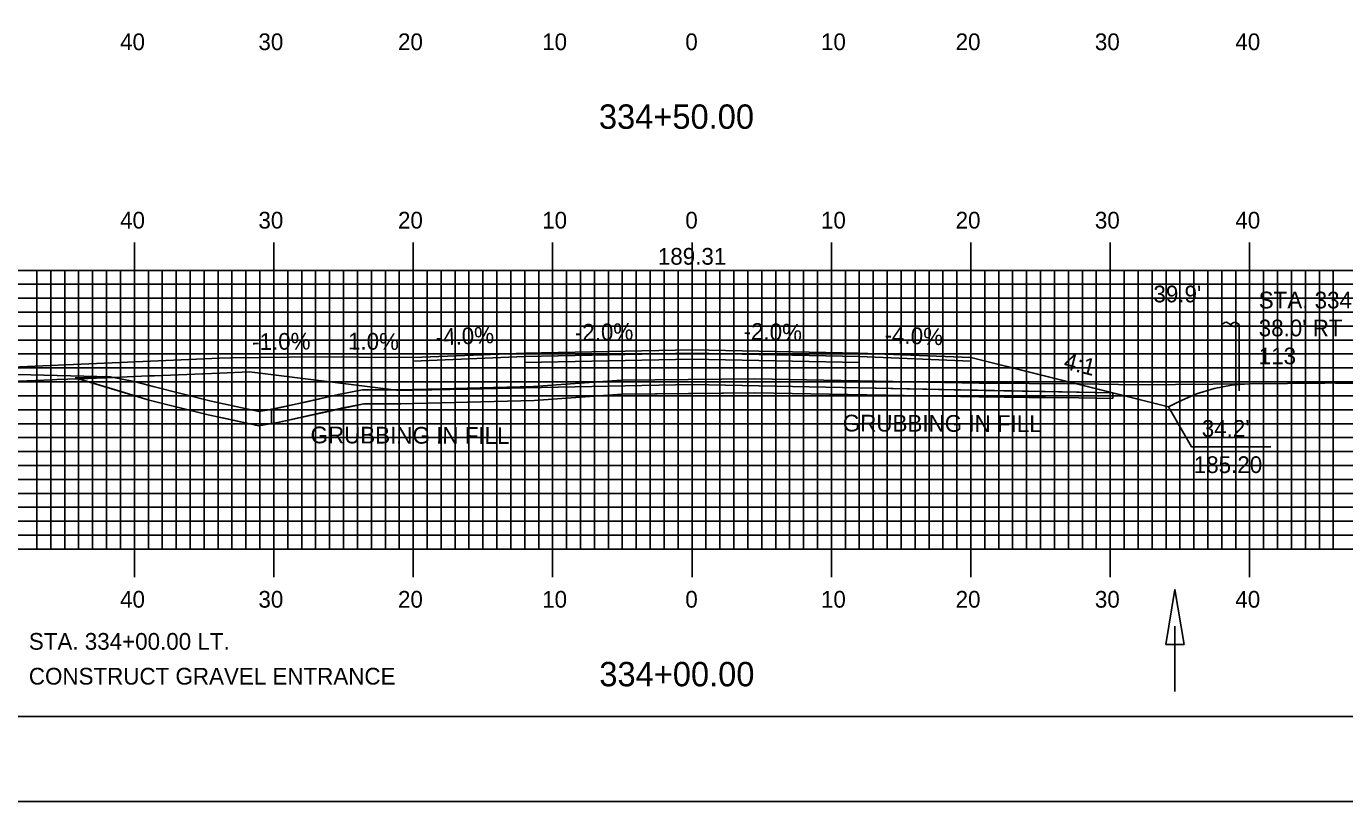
# Model space of a CAD drawing. Extents: x 1823179 to 1823522, y 442591 to 442811.
# Drawn here: x 1823297 to 1823391.6, y 442590.5 to 442646.2 of the extents above; entities that cross this region are included whole.
import ezdxf

# ---------------------------------------------------------------- set-up
doc = ezdxf.new("R2010")
doc.units = 0
for name, color, linetype in [('ANNOTATION', 7, 'Continuous'), ('BORDER', 7, 'Continuous'), ('D_Drainage_Ditch_Line', 7, 'Continuous'), ('D_Drainage_Text', 7, 'Continuous'), ('D_Roadway_Centerline', 7, 'Continuous'), ('D_Roadway_Centerline_Text', 7, 'Continuous'), ('D_Roadway_Drive_SubGrade', 7, 'Continuous'), ('D_Roadway_Edge_Shoulder', 7, 'Continuous'), ('D_Roadway_Edge_TW', 7, 'Continuous'), ('D_Roadway_FinishedGrade', 7, 'Continuous'), ('D_Roadway_Pavement', 7, 'Continuous'), ('D_Roadway_SlopeLines', 7, 'Continuous'), ('D_Roadway_SubGrade', 7, 'Continuous'), ('D_Text_Standard', 7, 'Continuous'), ('D_Utilities_Pole_Joint', 7, 'Continuous'), ('GRUBBING IN FILL', 7, 'Continuous'), ('H_V ANNOTATION', 7, 'Continuous'), ('MAJOR', 7, 'Continuous'), ('MINOR', 7, 'Continuous'), ('PLOT BOUNDARY', 7, 'Continuous'), ('S_Roadway_Centerline', 7, 'Continuous')]:
    doc.layers.add(name, color=color, linetype=linetype)

msp = doc.modelspace()

# ---------------------------------------------------------------- linework, layer by layer
at = {"layer": 'ANNOTATION'}
msp.add_line((1823310.906, 442622.367), (1823251.255, 442619.818), dxfattribs=at)
msp.add_lwpolyline([(1823386.318, 442615.997), (1823380.626, 442615.997), (1823378.97, 442618.867)], dxfattribs=at)
at = {"layer": 'BORDER'}
msp.add_lwpolyline([(1823195.196, 442596.665), (1823515.196, 442596.665), (1823515.196, 442806.665), (1823195.196, 442806.665)], close=True, dxfattribs=at)
at = {"layer": 'D_Drainage_Ditch_Line'}
msp.add_line((1823379.439, 442603.139), (1823379.439, 442598.44), dxfattribs=at)
msp.add_lwpolyline([(1823378.783, 442601.827), (1823380.095, 442601.827), (1823379.439, 442605.764)], close=True, dxfattribs=at)
at = {"layer": 'D_Roadway_Centerline'}
for points in [[(1823310.906, 442622.367), (1823310.907, 442622.367), (1823311.725, 442622.4), (1823311.741, 442622.4), (1823315.907, 442622.441), (1823318.796, 442622.47), (1823320.907, 442622.449), (1823324.796, 442622.41)], [(1823324.796, 442622.41), (1823332.796, 442622.73), (1823344.796, 442622.97), (1823356.796, 442622.73), (1823364.796, 442622.41), (1823374.97, 442619.867), (1823378.97, 442618.867), (1823379.739, 442619.251), (1823380.989, 442619.8), (1823382.239, 442620.195), (1823383.489, 442620.437), (1823384.739, 442620.526)]]:
    msp.add_lwpolyline(points, dxfattribs=at)
at = {"layer": 'D_Roadway_Drive_SubGrade'}
for p, q in [((1823323.796, 442620.05), (1823313.052, 442621.378)), ((1823324.796, 442620.07), (1823323.796, 442620.05))]:
    msp.add_line(p, q, dxfattribs=at)
msp.add_lwpolyline([(1823295.893, 442620.693), (1823298.932, 442620.815), (1823299.22, 442620.826), (1823300.798, 442620.889), (1823300.912, 442620.893), (1823302.64, 442620.962), (1823302.734, 442620.966), (1823305.825, 442621.09), (1823305.922, 442621.093), (1823306.235, 442621.106), (1823306.244, 442621.106), (1823309.709, 442621.245), (1823309.751, 442621.247), (1823310.917, 442621.293), (1823310.926, 442621.293), (1823313.052, 442621.378)], dxfattribs=at)
at = {"layer": 'D_Roadway_Edge_Shoulder'}
for points in [[(1823332.796, 442622.73), (1823324.796, 442622.41), (1823324.796, 442622.16), (1823332.796, 442622.48)], [(1823356.796, 442622.73), (1823364.796, 442622.41), (1823364.796, 442622.16), (1823356.796, 442622.48)]]:
    msp.add_lwpolyline(points, close=True, dxfattribs=at)
at = {"layer": 'D_Roadway_Edge_TW'}
msp.add_lwpolyline([(1823332.796, 442622.48), (1823332.796, 442622.73), (1823344.796, 442622.97), (1823356.796, 442622.73), (1823356.796, 442622.48), (1823344.796, 442622.72)], close=True, dxfattribs=at)
at = {"layer": 'D_Roadway_FinishedGrade'}
msp.add_line((1823324.796, 442622.41), (1823324.796, 442620.07), dxfattribs=at)
at = {"layer": 'D_Roadway_Pavement'}
msp.add_lwpolyline([(1823332.796, 442622.064), (1823332.796, 442622.48), (1823344.796, 442622.72), (1823356.796, 442622.48), (1823356.796, 442622.064), (1823344.796, 442622.304)], close=True, dxfattribs=at)
at = {"layer": 'D_Roadway_SlopeLines'}
for points in [[(1823364.796, 442622.41), (1823378.97, 442618.867)], [(1823378.97, 442618.867), (1823379.739, 442619.251), (1823380.989, 442619.8), (1823382.239, 442620.195), (1823383.489, 442620.437), (1823384.739, 442620.526)]]:
    msp.add_lwpolyline(points, dxfattribs=at)
at = {"layer": 'D_Roadway_SubGrade'}
msp.add_lwpolyline([(1823332.796, 442620.23), (1823324.796, 442620.07), (1823324.796, 442622.41), (1823324.796, 442622.16), (1823332.796, 442622.48), (1823344.796, 442622.72), (1823356.796, 442622.48), (1823364.796, 442622.16), (1823364.796, 442622.41), (1823374.97, 442619.867), (1823356.796, 442620.23), (1823344.796, 442620.47)], close=True, dxfattribs=at)
at = {"layer": 'D_Utilities_Pole_Joint'}
for p, q in [((1823382.796, 442624.777), (1823382.952, 442624.888)), ((1823383.264, 442624.888), (1823383.42, 442624.777)), ((1823383.576, 442624.888), (1823383.42, 442624.777)), ((1823384.046, 442624.777), (1823383.889, 442624.888)), ((1823382.796, 442620.02), (1823382.796, 442624.777)), ((1823383.42, 442624.777), (1823383.576, 442624.667)), ((1823383.889, 442624.667), (1823384.046, 442624.777)), ((1823384.046, 442620.02), (1823384.046, 442624.777))]:
    msp.add_line(p, q, dxfattribs=at)
for centre, start, end in [((1823383.108, 442624.667), 90, 125.26439), ((1823383.108, 442624.667), 54.73561, 90), ((1823383.733, 442624.667), 90, 125.26439), ((1823383.733, 442624.667), 54.73561, 90), ((1823383.733, 442624.888), 234.73561, 270), ((1823383.733, 442624.888), 270, 305.26439)]:
    msp.add_arc(centre, 0.271, start, end, dxfattribs=at)
at = {"layer": 'GRUBBING IN FILL'}
for p, q in [((1823374.97, 442619.867), (1823374.97, 442619.479)), ((1823374.97, 442619.867), (1823374.97, 442619.479)), ((1823314.621, 442617.669), (1823314.621, 442618.669)), ((1823314.621, 442617.669), (1823314.621, 442618.669))]:
    msp.add_line(p, q, dxfattribs=at)
for points in [[(1823300.549, 442620.952), (1823301.264, 442620.98), (1823302.728, 442621.039), (1823303.069, 442621.031), (1823303.929, 442620.856), (1823304.788, 442620.681), (1823305.429, 442620.531), (1823305.78, 442620.426), (1823306.131, 442620.321), (1823310.303, 442619.279), (1823313.294, 442618.634), (1823313.723, 442618.533), (1823314.302, 442618.63), (1823317.161, 442619.243), (1823319.441, 442619.76), (1823321.169, 442620.094), (1823322.532, 442620.094), (1823323.438, 442620.094), (1823323.796, 442620.05), (1823324.796, 442620.07), (1823328.796, 442620.15), (1823332.796, 442620.23), (1823338.796, 442620.35), (1823344.796, 442620.47), (1823344.796, 442619.833), (1823339.786, 442619.788), (1823333.462, 442619.34), (1823328.685, 442619.217), (1823323.908, 442619.095), (1823321.264, 442619.094), (1823315.073, 442617.745), (1823314.382, 442617.629), (1823313.69, 442617.514), (1823313.074, 442617.659), (1823311.575, 442617.982), (1823310.076, 442618.305), (1823307.971, 442618.831), (1823305.866, 442619.356), (1823303.207, 442620.154)], [(1823300.549, 442620.952), (1823301.264, 442620.98), (1823302.728, 442621.039), (1823303.069, 442621.031), (1823303.929, 442620.856), (1823304.788, 442620.681), (1823305.429, 442620.531), (1823305.78, 442620.426), (1823306.131, 442620.321), (1823310.303, 442619.279), (1823313.294, 442618.634), (1823313.723, 442618.533), (1823314.302, 442618.63), (1823317.161, 442619.243), (1823319.441, 442619.76), (1823321.169, 442620.094), (1823322.532, 442620.094), (1823323.438, 442620.094), (1823323.796, 442620.05), (1823324.796, 442620.07), (1823328.796, 442620.15), (1823332.796, 442620.23), (1823338.796, 442620.35), (1823344.796, 442620.47), (1823344.796, 442619.833), (1823339.786, 442619.788), (1823333.462, 442619.34), (1823328.685, 442619.217), (1823323.908, 442619.095), (1823321.264, 442619.094), (1823315.073, 442617.745), (1823314.382, 442617.629), (1823313.69, 442617.514), (1823313.074, 442617.659), (1823311.575, 442617.982), (1823310.076, 442618.305), (1823307.971, 442618.831), (1823305.866, 442619.356), (1823303.207, 442620.154)], [(1823344.796, 442620.47), (1823350.796, 442620.35), (1823356.796, 442620.23), (1823365.883, 442620.048), (1823374.97, 442619.867), (1823374.97, 442619.479), (1823372.553, 442619.521), (1823368.967, 442619.551), (1823365.382, 442619.581), (1823357.345, 442619.727), (1823349.308, 442619.873), (1823344.796, 442619.833)], [(1823344.796, 442620.47), (1823350.796, 442620.35), (1823356.796, 442620.23), (1823365.883, 442620.048), (1823374.97, 442619.867), (1823374.97, 442619.479), (1823372.553, 442619.521), (1823368.967, 442619.551), (1823365.382, 442619.581), (1823357.345, 442619.727), (1823349.308, 442619.873), (1823344.796, 442619.833)]]:
    msp.add_lwpolyline(points, close=True, dxfattribs=at)
for points in [[(1823300.549, 442620.952), (1823305.866, 442619.356), (1823310.076, 442618.305), (1823313.074, 442617.659), (1823313.69, 442617.514), (1823315.073, 442617.745), (1823319.647, 442618.781), (1823321.264, 442619.094), (1823323.908, 442619.095), (1823333.462, 442619.34), (1823339.786, 442619.788), (1823349.308, 442619.873), (1823365.382, 442619.581), (1823372.553, 442619.521), (1823374.97, 442619.479)], [(1823300.549, 442620.952), (1823305.866, 442619.356), (1823310.076, 442618.305), (1823313.074, 442617.659), (1823313.69, 442617.514), (1823315.073, 442617.745), (1823319.647, 442618.781), (1823321.264, 442619.094), (1823323.908, 442619.095), (1823333.462, 442619.34), (1823339.786, 442619.788), (1823349.308, 442619.873), (1823365.382, 442619.581), (1823372.553, 442619.521), (1823374.97, 442619.479)], [(1823314.621, 442617.669), (1823315.073, 442617.745), (1823319.647, 442618.781), (1823321.264, 442619.094), (1823323.438, 442619.094)], [(1823314.621, 442617.669), (1823315.073, 442617.745), (1823319.647, 442618.781), (1823321.264, 442619.094), (1823323.438, 442619.094)]]:
    msp.add_lwpolyline(points, dxfattribs=at)
at = {"layer": 'MAJOR'}
for p, q in [((1823304.796, 442630.669), (1823304.796, 442628.665)), ((1823314.796, 442630.669), (1823314.796, 442628.665)), ((1823324.796, 442630.669), (1823324.796, 442628.665)), ((1823334.796, 442630.669), (1823334.796, 442628.665)), ((1823344.796, 442630.669), (1823344.796, 442628.665)), ((1823354.796, 442630.669), (1823354.796, 442628.665)), ((1823364.796, 442630.669), (1823364.796, 442628.665)), ((1823374.796, 442630.669), (1823374.796, 442628.665)), ((1823384.796, 442630.669), (1823384.796, 442628.665)), ((1823204.796, 442628.665), (1823484.796, 442628.665)), ((1823204.796, 442628.665), (1823484.796, 442628.665)), ((1823304.796, 442608.665), (1823304.796, 442628.665)), ((1823314.796, 442608.665), (1823314.796, 442628.665)), ((1823324.796, 442608.665), (1823324.796, 442628.665)), ((1823334.796, 442608.665), (1823334.796, 442628.665)), ((1823344.796, 442608.665), (1823344.796, 442628.665)), ((1823354.796, 442608.665), (1823354.796, 442628.665)), ((1823364.796, 442608.665), (1823364.796, 442628.665)), ((1823374.796, 442608.665), (1823374.796, 442628.665)), ((1823384.796, 442608.665), (1823384.796, 442628.665)), ((1823204.796, 442623.665), (1823484.796, 442623.665)), ((1823204.796, 442618.665), (1823484.796, 442618.665)), ((1823204.796, 442613.665), (1823484.796, 442613.665)), ((1823204.796, 442608.665), (1823484.796, 442608.665)), ((1823204.796, 442608.665), (1823484.796, 442608.665)), ((1823304.796, 442606.661), (1823304.796, 442608.665)), ((1823314.796, 442606.661), (1823314.796, 442608.665)), ((1823324.796, 442606.661), (1823324.796, 442608.665)), ((1823334.796, 442606.661), (1823334.796, 442608.665)), ((1823344.796, 442606.661), (1823344.796, 442608.665)), ((1823354.796, 442606.661), (1823354.796, 442608.665)), ((1823364.796, 442606.661), (1823364.796, 442608.665)), ((1823374.796, 442606.661), (1823374.796, 442608.665)), ((1823384.796, 442606.661), (1823384.796, 442608.665))]:
    msp.add_line(p, q, dxfattribs=at)
at = {"layer": 'MINOR'}
for p, q in [((1823297.796, 442608.665), (1823297.796, 442628.665)), ((1823298.796, 442608.665), (1823298.796, 442628.665)), ((1823299.796, 442608.665), (1823299.796, 442628.665)), ((1823300.796, 442608.665), (1823300.796, 442628.665)), ((1823301.796, 442608.665), (1823301.796, 442628.665)), ((1823302.796, 442608.665), (1823302.796, 442628.665)), ((1823303.796, 442608.665), (1823303.796, 442628.665)), ((1823305.796, 442608.665), (1823305.796, 442628.665)), ((1823306.796, 442608.665), (1823306.796, 442628.665)), ((1823307.796, 442608.665), (1823307.796, 442628.665)), ((1823308.796, 442608.665), (1823308.796, 442628.665)), ((1823309.796, 442608.665), (1823309.796, 442628.665)), ((1823310.796, 442608.665), (1823310.796, 442628.665)), ((1823311.796, 442608.665), (1823311.796, 442628.665)), ((1823312.796, 442608.665), (1823312.796, 442628.665)), ((1823313.796, 442608.665), (1823313.796, 442628.665)), ((1823315.796, 442608.665), (1823315.796, 442628.665)), ((1823316.796, 442608.665), (1823316.796, 442628.665)), ((1823317.796, 442608.665), (1823317.796, 442628.665)), ((1823318.796, 442608.665), (1823318.796, 442628.665)), ((1823319.796, 442608.665), (1823319.796, 442628.665)), ((1823320.796, 442608.665), (1823320.796, 442628.665)), ((1823321.796, 442608.665), (1823321.796, 442628.665)), ((1823322.796, 442608.665), (1823322.796, 442628.665)), ((1823323.796, 442608.665), (1823323.796, 442628.665)), ((1823325.796, 442608.665), (1823325.796, 442628.665)), ((1823326.796, 442608.665), (1823326.796, 442628.665)), ((1823327.796, 442608.665), (1823327.796, 442628.665)), ((1823328.796, 442608.665), (1823328.796, 442628.665)), ((1823329.796, 442608.665), (1823329.796, 442628.665)), ((1823330.796, 442608.665), (1823330.796, 442628.665)), ((1823331.796, 442608.665), (1823331.796, 442628.665)), ((1823332.796, 442608.665), (1823332.796, 442628.665)), ((1823333.796, 442608.665), (1823333.796, 442628.665)), ((1823335.796, 442608.665), (1823335.796, 442628.665)), ((1823336.796, 442608.665), (1823336.796, 442628.665)), ((1823337.796, 442608.665), (1823337.796, 442628.665)), ((1823338.796, 442608.665), (1823338.796, 442628.665)), ((1823339.796, 442608.665), (1823339.796, 442628.665)), ((1823340.796, 442608.665), (1823340.796, 442628.665)), ((1823341.796, 442608.665), (1823341.796, 442628.665)), ((1823342.796, 442608.665), (1823342.796, 442628.665)), ((1823343.796, 442608.665), (1823343.796, 442628.665)), ((1823345.796, 442608.665), (1823345.796, 442628.665)), ((1823346.796, 442608.665), (1823346.796, 442628.665)), ((1823347.796, 442608.665), (1823347.796, 442628.665)), ((1823348.796, 442608.665), (1823348.796, 442628.665)), ((1823349.796, 442608.665), (1823349.796, 442628.665)), ((1823350.796, 442608.665), (1823350.796, 442628.665)), ((1823351.796, 442608.665), (1823351.796, 442628.665)), ((1823352.796, 442608.665), (1823352.796, 442628.665)), ((1823353.796, 442608.665), (1823353.796, 442628.665)), ((1823355.796, 442608.665), (1823355.796, 442628.665)), ((1823356.796, 442608.665), (1823356.796, 442628.665)), ((1823357.796, 442608.665), (1823357.796, 442628.665)), ((1823358.796, 442608.665), (1823358.796, 442628.665)), ((1823359.796, 442608.665), (1823359.796, 442628.665)), ((1823360.796, 442608.665), (1823360.796, 442628.665)), ((1823361.796, 442608.665), (1823361.796, 442628.665)), ((1823362.796, 442608.665), (1823362.796, 442628.665)), ((1823363.796, 442608.665), (1823363.796, 442628.665)), ((1823365.796, 442608.665), (1823365.796, 442628.665)), ((1823366.796, 442608.665), (1823366.796, 442628.665)), ((1823367.796, 442608.665), (1823367.796, 442628.665)), ((1823368.796, 442608.665), (1823368.796, 442628.665)), ((1823369.796, 442608.665), (1823369.796, 442628.665)), ((1823370.796, 442608.665), (1823370.796, 442628.665)), ((1823371.796, 442608.665), (1823371.796, 442628.665)), ((1823372.796, 442608.665), (1823372.796, 442628.665)), ((1823373.796, 442608.665), (1823373.796, 442628.665)), ((1823375.796, 442608.665), (1823375.796, 442628.665)), ((1823376.796, 442608.665), (1823376.796, 442628.665)), ((1823377.796, 442608.665), (1823377.796, 442628.665)), ((1823378.796, 442608.665), (1823378.796, 442628.665)), ((1823379.796, 442608.665), (1823379.796, 442628.665)), ((1823380.796, 442608.665), (1823380.796, 442628.665)), ((1823381.796, 442608.665), (1823381.796, 442628.665)), ((1823382.796, 442608.665), (1823382.796, 442628.665)), ((1823383.796, 442608.665), (1823383.796, 442628.665)), ((1823385.796, 442608.665), (1823385.796, 442628.665)), ((1823386.796, 442608.665), (1823386.796, 442628.665)), ((1823387.796, 442608.665), (1823387.796, 442628.665)), ((1823388.796, 442608.665), (1823388.796, 442628.665)), ((1823389.796, 442608.665), (1823389.796, 442628.665)), ((1823390.796, 442608.665), (1823390.796, 442628.665)), ((1823204.796, 442627.665), (1823484.796, 442627.665)), ((1823204.796, 442626.665), (1823484.796, 442626.665)), ((1823204.796, 442625.665), (1823484.796, 442625.665)), ((1823204.796, 442624.665), (1823484.796, 442624.665)), ((1823204.796, 442622.665), (1823484.796, 442622.665)), ((1823204.796, 442621.665), (1823484.796, 442621.665)), ((1823204.796, 442620.665), (1823484.796, 442620.665)), ((1823204.796, 442619.665), (1823484.796, 442619.665)), ((1823204.796, 442617.665), (1823484.796, 442617.665)), ((1823204.796, 442616.665), (1823484.796, 442616.665)), ((1823204.796, 442615.665), (1823484.796, 442615.665)), ((1823204.796, 442614.665), (1823484.796, 442614.665)), ((1823204.796, 442612.665), (1823484.796, 442612.665)), ((1823204.796, 442611.665), (1823484.796, 442611.665)), ((1823204.796, 442610.665), (1823484.796, 442610.665)), ((1823204.796, 442609.665), (1823484.796, 442609.665))]:
    msp.add_line(p, q, dxfattribs=at)
at = {"layer": 'PLOT BOUNDARY'}
msp.add_lwpolyline([(1823179.009, 442590.547), (1823519.009, 442590.547), (1823519.009, 442810.547), (1823179.009, 442810.547)], close=True, dxfattribs=at)
at = {"layer": 'S_Roadway_Centerline'}
msp.add_lwpolyline([(1823296.409, 442621.188), (1823303.069, 442621.031), (1823304.788, 442620.681), (1823305.429, 442620.531), (1823306.131, 442620.321), (1823310.303, 442619.279), (1823313.294, 442618.634), (1823313.723, 442618.533), (1823314.88, 442618.726), (1823319.441, 442619.76), (1823321.169, 442620.094), (1823323.895, 442620.095), (1823333.414, 442620.339), (1823339.746, 442620.788), (1823349.312, 442620.873), (1823365.395, 442620.581), (1823372.566, 442620.521), (1823376.793, 442620.448), (1823390.181, 442620.579), (1823390.364, 442620.584), (1823390.964, 442620.577), (1823404.58, 442620.499)], dxfattribs=at)

# ---------------------------------------------------------------- texts
at = {"layer": 'ANNOTATION'}
for s, rotation, p in [('-2.0%', 1.14576, (1823336.402, 442623.603)), ('-2.0%', 358.85424, (1823348.482, 442623.697)), ('-1.0%', 0.57294, (1823313.243, 442622.949)), ('1.0%', 359.42706, (1823320.11, 442622.991)), ('-4.0%', 2.29061, (1823326.427, 442623.277)), ('-4.0%', 357.70939, (1823358.587, 442623.46)), ('4:1', 345.96376, (1823371.388, 442621.624))]:
    msp.add_text(s, height=1.2, rotation=rotation, dxfattribs=at).set_placement(p)
for s, p in [("34.2'", (1823381.361, 442616.723)), ('185.20', (1823380.788, 442614.123))]:
    msp.add_text(s, height=1.2, dxfattribs=at).set_placement(p)
at = {"layer": 'D_Drainage_Text'}
for s, p in [('STA. 334+25.00', (1823385.446, 442625.935)), ("38.0' RT", (1823385.446, 442623.931)), ('113', (1823385.446, 442621.927))]:
    msp.add_text(s, height=1.2, dxfattribs=at).set_placement(p)
at = {"layer": 'D_Roadway_Centerline'}
for s, p in [('C', (1823344.79, 442622.97)), ('L', (1823344.796, 442622.963))]:
    msp.add_text(s, height=0.0146, dxfattribs=at).set_placement(p)
at = {"layer": 'D_Roadway_Centerline_Text'}
msp.add_text('189.31', height=1.2, dxfattribs=at).set_placement((1823342.345, 442629.072))
at = {"layer": 'D_Text_Standard'}
for s, p in [("39.9'", (1823377.893, 442626.37)), ('STA. 334+00.00 LT.', (1823297.224, 442601.446)), ('STA. 334+00.00 LT.', (1823297.224, 442601.446)), ('CONSTRUCT GRAVEL ENTRANCE', (1823297.224, 442598.946)), ('CONSTRUCT GRAVEL ENTRANCE', (1823297.224, 442598.946))]:
    msp.add_text(s, height=1.2, dxfattribs=at).set_placement(p)
at = {"layer": 'GRUBBING IN FILL'}
for p in [(1823355.612, 442617.109), (1823317.432, 442616.259)]:
    msp.add_text('GRUBBING IN FILL', height=1.2, rotation=359.80532, dxfattribs=at).set_placement(p)
at = {"layer": 'H_V ANNOTATION'}
for s, height, p in [('40', 1.2, (1823303.768, 442644.465)), ('30', 1.2, (1823313.693, 442644.465)), ('20', 1.2, (1823323.704, 442644.465)), ('10', 1.2, (1823334.046, 442644.465)), ('0', 1.2, (1823344.314, 442644.465)), ('10', 1.2, (1823354.046, 442644.465)), ('20', 1.2, (1823363.704, 442644.465)), ('30', 1.2, (1823373.693, 442644.465)), ('40', 1.2, (1823383.768, 442644.465)), ('334+50.00', 1.75, (1823338.116, 442638.821)), ('40', 1.2, (1823303.768, 442631.665)), ('30', 1.2, (1823313.693, 442631.665)), ('20', 1.2, (1823323.704, 442631.665)), ('10', 1.2, (1823334.046, 442631.665)), ('0', 1.2, (1823344.314, 442631.665)), ('10', 1.2, (1823354.046, 442631.665)), ('20', 1.2, (1823363.704, 442631.665)), ('30', 1.2, (1823373.693, 442631.665)), ('40', 1.2, (1823383.768, 442631.665)), ('40', 1.2, (1823303.768, 442604.465)), ('30', 1.2, (1823313.693, 442604.465)), ('20', 1.2, (1823323.704, 442604.465)), ('10', 1.2, (1823334.046, 442604.465)), ('0', 1.2, (1823344.314, 442604.465)), ('10', 1.2, (1823354.046, 442604.465)), ('20', 1.2, (1823363.704, 442604.465)), ('30', 1.2, (1823373.693, 442604.465)), ('40', 1.2, (1823383.768, 442604.465)), ('334+00.00', 1.75, (1823338.147, 442598.821))]:
    msp.add_text(s, height=height, dxfattribs=at).set_placement(p)

doc.saveas('drawing.dxf')
